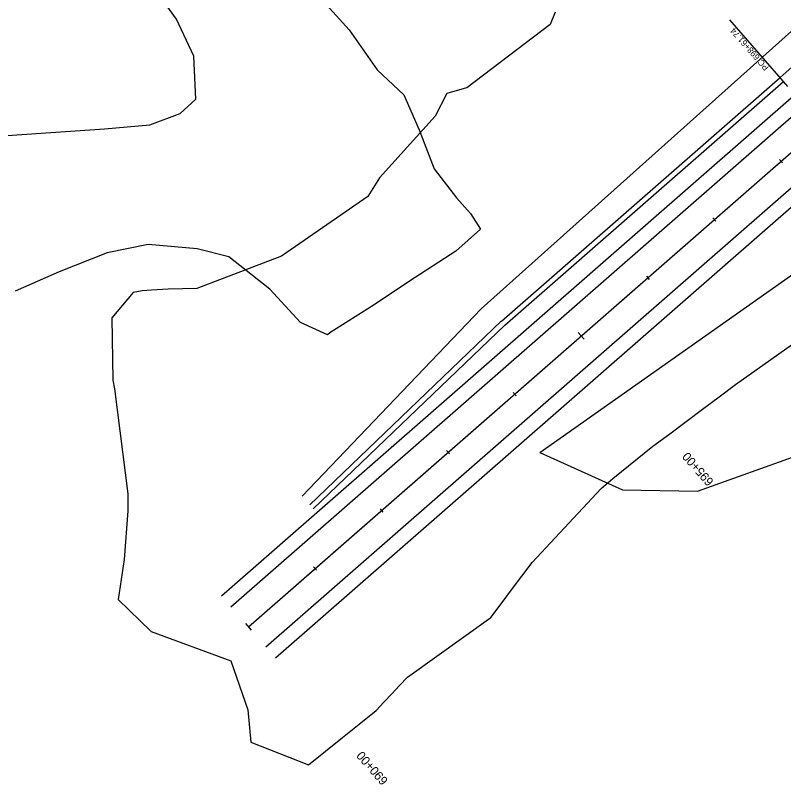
# Model space of a CAD drawing. Extents: x 1300404 to 1323571, y 234004 to 252077.
# Drawn here: x 1308164 to 1309033, y 238758 to 239629 of the extents above; entities that cross this region are included whole.
import ezdxf

# ---------------------------------------------------------------- set-up
doc = ezdxf.new("R2010")
doc.units = 0
for name, color, linetype in [('R_Const Limits', 7, 'Continuous'), ('R_Draft', 7, 'Continuous'), ('R_Flooplain', 7, 'Continuous'), ('R_Horz Alg Annot', 7, 'Continuous'), ('R_Horz Alg Annot Leader', 7, 'Continuous'), ('R_Horz Alg Major Ticks', 7, 'Continuous'), ('R_Horz Alg Minor Ticks', 7, 'Continuous'), ('R_Horz Alg Station Annot', 7, 'Continuous'), ('R_Lane Edge', 7, 'Continuous'), ('R_Proposed', 7, 'Continuous'), ('R_Shoulder', 7, 'Continuous')]:
    doc.layers.add(name, color=color, linetype=linetype)

msp = doc.modelspace()

# ---------------------------------------------------------------- linework, layer by layer
at = {"layer": 'R_Const Limits'}
for points in [[(1309161.24, 239746.22), (1309174.84, 239731.08), (1309163.84, 239720.33), (1309126.38, 239686.18), (1309041.87, 239610.58), (1308690.69, 239296.76), (1308488.36, 239084.81)], [(1308774.64, 239632.28), (1308768.84, 239618.23), (1308674.56, 239546.48), (1308671.44, 239545.82), (1308651.79, 239540.06), (1308638.96, 239514.4), (1308575.75, 239444.78), (1308562.79, 239423.6), (1308465.14, 239356.04), (1308369.19, 239319.48), (1308336.7, 239318.92), (1308317.83, 239317.78), (1308307.43, 239316.97), (1308297.26, 239315.04), (1308273.27, 239286.31), (1308274.18, 239216.03), (1308276.04, 239206.06), (1308291.24, 239087.38), (1308291.07, 239068.07), (1308287.24, 239013.23), (1308280.27, 238967.85), (1308317.57, 238931.84), (1308407.52, 238898.52), (1308426.94, 238843.02), (1308430.16, 238806.53), (1308495.71, 238781.01), (1308514.77, 238796.34), (1308533.82, 238811.67), (1308552.88, 238827), (1308571.94, 238842.33), (1308580.81, 238851.79), (1308589.68, 238861.25), (1308598.55, 238870.71), (1308607.41, 238880.17), (1308701.84, 238947.53), (1308713.48, 238963.09), (1308725.11, 238978.65), (1308736.75, 238994.21), (1308748.38, 239009.77), (1308826.6, 239093.41), (1308839.73, 239104.68), (1308885, 239141.21), (1308904, 239155.19), (1308922.62, 239169.16), (1308941.24, 239183.13), (1308959.86, 239197.1), (1308978.49, 239211.07), (1309067.29, 239274.12)]]:
    msp.add_lwpolyline(points, dxfattribs=at)
at = {"layer": 'R_Draft'}
for p, q in [((1308396.96, 238971.92), (1312368.36, 242444.53)), ((1308407.83, 238959.5), (1312379.22, 242432.11)), ((1308447.32, 238914.33), (1312418.71, 242386.94)), ((1308458.18, 238901.91), (1312429.57, 242374.52))]:
    msp.add_line(p, q, dxfattribs=at)
at = {"layer": 'R_Flooplain'}
for p, q in [((1308346.19, 239624.41), (1308328.08, 239649.52)), ((1308502.57, 239655.25), (1308541.56, 239612.15)), ((1308365.87, 239582.29), (1308346.19, 239624.41)), ((1308541.56, 239612.15), (1308573.18, 239567)), ((1308368.29, 239533.77), (1308365.87, 239582.29)), ((1308573.18, 239567), (1308603.24, 239538.87)), ((1308603.24, 239538.87), (1308620.62, 239499.29)), ((1308350.55, 239517.73), (1308368.29, 239533.77)), ((1308316.04, 239504.95), (1308350.55, 239517.73)), ((1308265, 239500.27), (1308316.04, 239504.95)), ((1308121.76, 239490.54), (1308204.3, 239496.06)), ((1308204.3, 239496.06), (1308265, 239500.27)), ((1308620.62, 239499.29), (1308637.76, 239454.87)), ((1308637.76, 239454.87), (1308662.75, 239422.16)), ((1308662.75, 239422.16), (1308678.8, 239404.41)), ((1308678.8, 239404.41), (1308690.03, 239386.91)), ((1308690.03, 239386.91), (1308662.16, 239361.7)), ((1308757.29, 239134.3), (1309093.32, 239371.43)), ((1308314.14, 239369.55), (1308267.68, 239359.79)), ((1308369.53, 239364.34), (1308314.14, 239369.55)), ((1308405.37, 239355.28), (1308369.53, 239364.34)), ((1308267.68, 239359.79), (1308213.38, 239338.33)), ((1308451.95, 239319.05), (1308405.37, 239355.28)), ((1308662.16, 239361.7), (1308609.67, 239328.05)), ((1308213.38, 239338.33), (1308163.91, 239316.63)), ((1308609.67, 239328.05), (1308569.61, 239301.03)), ((1308486.35, 239281.03), (1308451.95, 239319.05)), ((1308569.61, 239301.03), (1308519.66, 239269.67)), ((1308517.13, 239267.38), (1308486.35, 239281.03)), ((1308519.66, 239269.67), (1308517.13, 239267.38)), ((1308757.29, 239134.3), (1308850.76, 239092.09)), ((1308935.35, 239090.24), (1309053.6, 239132.68)), ((1308850.76, 239092.09), (1308935.35, 239090.24))]:
    msp.add_line(p, q, dxfattribs=at)
at = {"layer": 'R_Horz Alg Annot Leader'}
msp.add_lwpolyline([(1309037.78, 239548.19), (1308971.95, 239623.47)], dxfattribs=at)
at = {"layer": 'R_Horz Alg Major Ticks'}
for points in [[(1308800.68, 239269.8), (1308807.26, 239262.27)], [(1308424.28, 238940.68), (1308430.86, 238933.15)], [(1308425.92, 238938.79), (1308429.22, 238935.03)]]:
    msp.add_lwpolyline(points, dxfattribs=at)
at = {"layer": 'R_Horz Alg Minor Ticks'}
for points in [[(1309028.16, 239465.39), (1309031.45, 239461.63)], [(1308952.88, 239399.57), (1308956.17, 239395.8)], [(1308877.6, 239333.74), (1308880.89, 239329.98)], [(1308727.04, 239202.09), (1308730.33, 239198.33)], [(1308651.76, 239136.27), (1308655.06, 239132.5)], [(1308576.48, 239070.44), (1308579.78, 239066.68)], [(1308501.2, 239004.62), (1308504.5, 239000.85)]]:
    msp.add_lwpolyline(points, dxfattribs=at)
at = {"layer": 'R_Lane Edge'}
for p, q in [((1308717.71, 239278.28), (1309032.84, 239553.84)), ((1308500.81, 239070.58), (1308717.71, 239278.28))]:
    msp.add_line(p, q, dxfattribs=at)
at = {"layer": 'R_Proposed'}
for p, q in [((1308463.14, 238968.01), (1312793.8, 242754.77)), ((1308427.57, 238936.91), (1312398.96, 242409.52))]:
    msp.add_line(p, q, dxfattribs=at)
at = {"layer": 'R_Shoulder'}
for p, q in [((1308713.67, 239282.72), (1309028.89, 239558.35)), ((1308496.86, 239075.1), (1308713.56, 239282.62))]:
    msp.add_line(p, q, dxfattribs=at)
msp.add_arc((1305266.27, 243861.41), 5716.08, 311.16667, 314.02346, dxfattribs=at)

# ---------------------------------------------------------------- texts
at = {"layer": 'R_Horz Alg Annot'}
msp.add_text('PC 698+61.74', height=7, rotation=131.16667, dxfattribs=at).set_placement((1309016.77, 239569.94))
at = {"layer": 'R_Horz Alg Station Annot'}
for s, p in [('695+00', (1308954.44, 239101.61)), ('690+00', (1308586.07, 238763.35))]:
    msp.add_text(s, height=10, rotation=131.16667, dxfattribs=at).set_placement(p)

doc.saveas('drawing.dxf')
